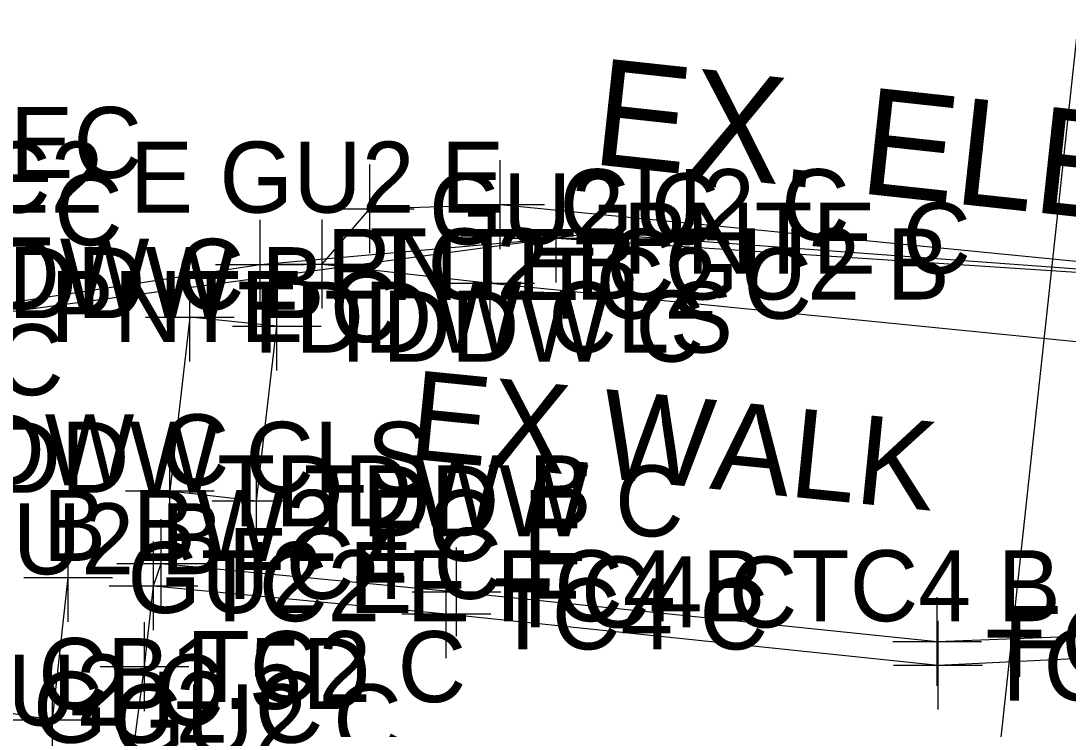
# Model space of a CAD drawing. Extents: x 1363693 to 1365209, y 422201 to 424153.
# Drawn here: x 1364031.26 to 1364054.86, y 423089.1 to 423105.06 of the extents above; entities that cross this region are included whole.
import ezdxf

# ---------------------------------------------------------------- set-up
doc = ezdxf.new("R2010")
doc.units = 0
for name, color, linetype in [('BASELINE-CL-RW', 7, 'Continuous'), ('DR_X_Storm_Sewer', 7, 'Continuous'), ('O-ALGN-TEXT-BASELINE-WERK-CL-RW', 7, 'Continuous'), ('OWNERS', 7, 'Continuous'), ('RD_X_Misc_Items', 7, 'Continuous'), ('RD_X_Text', 7, 'Continuous'), ('SV_X_Original_Ground', 7, 'Continuous'), ('SV_X_Random_Point', 7, 'Continuous'), ('SV_X_Shot_Marker', 7, 'Continuous'), ('UT_X_Electric', 7, 'Continuous'), ('UT_X_Electric_Text', 7, 'Continuous')]:
    doc.layers.add(name, color=color, linetype=linetype)

msp = doc.modelspace()

# ---------------------------------------------------------------- linework, layer by layer
at = {"layer": 'BASELINE-CL-RW'}
for points in [[(1364038.047, 423099.579), (1364041.836, 423099.146), (1364066.67, 423096.675), (1364068.189, 423096.673), (1364092.147, 423099.618), (1364115.311, 423102.579), (1364117.714, 423103.085), (1364123.598, 423104.457), (1364142.807, 423102.331)], [(1364034.246, 423092.33), (1364040.848, 423091.696), (1364051.931, 423090.54), (1364060.837, 423090.978)]]:
    msp.add_lwpolyline(points, dxfattribs=at)
at = {"layer": 'DR_X_Storm_Sewer'}
msp.add_line((1364037.894, 422945.787), (1364082.792, 423361.415), dxfattribs=at)
at = {"layer": 'O-ALGN-TEXT-BASELINE-WERK-CL-RW'}
msp.add_lwpolyline([(1364034.246, 423092.33), (1364034.422, 423092.833), (1364041.078, 423092.19), (1364051.909, 423091.071), (1364061.127, 423091.426)], dxfattribs=at)
at = {"layer": 'OWNERS'}
for points in [[(1364038.047, 423099.579), (1364039.122, 423100.823), (1364042.065, 423100.916), (1364066.805, 423098.487), (1364068.345, 423098.45), (1364092.357, 423101.333), (1364115.457, 423104.165), (1364117.827, 423104.314), (1364123.662, 423105.003)], [(1364026.047, 423093.689), (1364025.683, 423088.22), (1364033.626, 423087.325), (1364034.043, 423090.507), (1364034.246, 423092.33)], [(1364028.074, 423093.389), (1364027.957, 423089.98), (1364030.198, 423089.591), (1364031.969, 423089.31), (1364032.323, 423092.515)]]:
    msp.add_lwpolyline(points, dxfattribs=at)
at = {"layer": 'RD_X_Misc_Items'}
for p, q in [((1364035.065, 423098.382), (1364034.614, 423094.468)), ((1364035.065, 423098.382), (1364034.614, 423094.468)), ((1364037.027, 423098.178), (1364035.065, 423098.382)), ((1364037.027, 423098.178), (1364035.065, 423098.382)), ((1364036.57, 423094.242), (1364037.027, 423098.178)), ((1364036.57, 423094.242), (1364037.027, 423098.178)), ((1364034.614, 423094.468), (1364036.57, 423094.242)), ((1364034.614, 423094.468), (1364036.57, 423094.242))]:
    msp.add_line(p, q, dxfattribs=at)
at = {"layer": 'SV_X_Original_Ground'}
for p, q in [((1364035.065, 423097.382), (1364035.065, 423099.382)), ((1364037.027, 423097.178), (1364037.027, 423099.178)), ((1364034.065, 423098.382), (1364036.065, 423098.382)), ((1364036.027, 423098.178), (1364038.027, 423098.178)), ((1364034.614, 423093.468), (1364034.614, 423095.468)), ((1364036.57, 423093.242), (1364036.57, 423095.242)), ((1364033.614, 423094.468), (1364035.614, 423094.468)), ((1364035.57, 423094.242), (1364037.57, 423094.242))]:
    msp.add_line(p, q, dxfattribs=at)
at = {"layer": 'SV_X_Random_Point'}
for p, q in [((1364043.325, 423099.162), (1364043.325, 423101.162)), ((1364036.649, 423098.571), (1364036.649, 423100.571)), ((1364042.325, 423100.162), (1364044.325, 423100.162)), ((1364035.649, 423099.571), (1364037.649, 423099.571)), ((1364029.424, 423098.618), (1364031.424, 423098.618))]:
    msp.add_line(p, q, dxfattribs=at)
at = {"layer": 'SV_X_Shot_Marker'}
for p, q in [((1364039.122, 423099.823), (1364039.122, 423101.823)), ((1364042.065, 423099.916), (1364042.065, 423101.916)), ((1364038.122, 423100.823), (1364040.122, 423100.823)), ((1364041.065, 423100.916), (1364043.065, 423100.916)), ((1364038.047, 423098.579), (1364038.047, 423100.579)), ((1364041.836, 423098.146), (1364041.836, 423100.146)), ((1364037.047, 423099.579), (1364039.047, 423099.579)), ((1364040.836, 423099.146), (1364042.836, 423099.146)), ((1364034.422, 423091.833), (1364034.422, 423093.833)), ((1364032.323, 423091.515), (1364032.323, 423093.515)), ((1364034.246, 423091.33), (1364034.246, 423093.33)), ((1364041.078, 423091.19), (1364041.078, 423093.19)), ((1364033.422, 423092.833), (1364035.422, 423092.833)), ((1364040.848, 423090.696), (1364040.848, 423092.696)), ((1364031.323, 423092.515), (1364033.323, 423092.515)), ((1364033.246, 423092.33), (1364035.246, 423092.33)), ((1364040.078, 423092.19), (1364042.078, 423092.19)), ((1364051.909, 423090.071), (1364051.909, 423092.071)), ((1364039.848, 423091.696), (1364041.848, 423091.696)), ((1364034.043, 423089.507), (1364034.043, 423091.507)), ((1364051.931, 423089.54), (1364051.931, 423091.54)), ((1364050.909, 423091.071), (1364052.909, 423091.071)), ((1364033.043, 423090.507), (1364035.043, 423090.507)), ((1364050.931, 423090.54), (1364052.931, 423090.54)), ((1364031.969, 423088.31), (1364031.969, 423090.31)), ((1364030.969, 423089.31), (1364032.969, 423089.31))]:
    msp.add_line(p, q, dxfattribs=at)
at = {"layer": 'UT_X_Electric'}
for p, q in [((1364036.649, 423099.571), (1364043.325, 423100.162)), ((1364043.325, 423100.162), (1364062.341, 423098.916)), ((1364030.424, 423098.618), (1364036.649, 423099.571))]:
    msp.add_line(p, q, dxfattribs=at)
msp.add_lwpolyline([(1364063.139, 423098.819), (1364061.842, 423098.964), (1364044.113, 423100.265), (1364024.23, 423097.585), (1364011.892, 423094.791), (1364006.837, 423093.546)], dxfattribs=at)

# ---------------------------------------------------------------- texts
at = {"layer": 'RD_X_Text'}
msp.add_text('EX.WALK', height=2, rotation=354.3031, dxfattribs=at).set_placement((1364039.961, 423095.199))
at = {"layer": 'SV_X_Original_Ground'}
for s, p in [('TDDW C', (1364027.739, 423098.547)), ('TDDW B', (1364029.666, 423098.359)), ('TDDW CLS', (1364036.136, 423097.582)), ('TDDW C', (1364038.098, 423097.378)), ('TDDW C', (1364027.4, 423094.592)), ('TDDW CLS', (1364029.308, 423094.423)), ('TDDW B', (1364035.685, 423093.668)), ('TDDW C', (1364037.641, 423093.442))]:
    msp.add_text(s, height=1.6, dxfattribs=at).set_placement(p)
at = {"layer": 'SV_X_Random_Point'}
for p in [(1364044.825, 423099.362), (1364038.149, 423098.771), (1364031.924, 423097.818), (1364024.38, 423096.623)]:
    msp.add_text('PNTE C', height=1.6, dxfattribs=at).set_placement(p)
at = {"layer": 'SV_X_Shot_Marker'}
for s, p in [('GU2 EC', (1364026.021, 423101.517)), ('TC2 E GU2 E', (1364029.076, 423100.736)), ('GU2 C', (1364043.402, 423100.116)), ('TC2 EC', (1364025.943, 423100.002)), ('GU2 C', (1364040.459, 423100.023)), ('TC2 B GU2 B', (1364039.118, 423098.779)), ('TC2 C', (1364042.907, 423098.346)), ('TC2 B BW2 EC E', (1364027.118, 423092.889)), ('GU2 B', (1364029.411, 423092.589)), ('FC4 C', (1364035.922, 423092.033)), ('GU2 E', (1364033.66, 423091.715)), ('TC2 E FC4 B TC4 B', (1364035.317, 423091.53)), ('FC4 C', (1364042.578, 423091.39)), ('TC4 C', (1364041.919, 423090.896)), ('FC4 C', (1364053.409, 423090.271)), ('TC4 C', (1364053.002, 423089.74)), ('CB1.5D', (1364031.65, 423089.551)), ('TC2 C', (1364035.114, 423089.707)), ('GU2 C', (1364029.294, 423089.18)), ('GU2 C', (1364031.535, 423088.791)), ('GU2 C', (1364033.306, 423088.51))]:
    msp.add_text(s, height=1.6, dxfattribs=at).set_placement(p)
at = {"layer": 'UT_X_Electric_Text'}
msp.add_text('EX. ELECTRIC', height=2.4, rotation=353.8006, dxfattribs=at).set_placement((1364044.086, 423101.835))

doc.saveas('drawing.dxf')
